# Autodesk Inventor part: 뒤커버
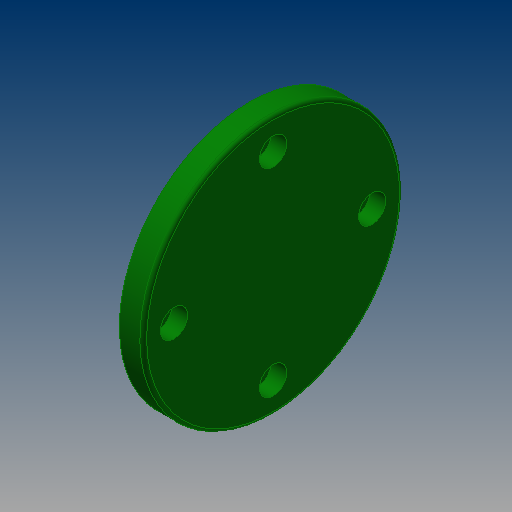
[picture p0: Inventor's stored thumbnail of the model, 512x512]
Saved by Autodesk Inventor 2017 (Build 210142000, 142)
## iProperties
Created: 2015-09
Part Number: 뒤커버
Material: 알루미늄 6061
Document SubType Name: Modeling
Designer: mduedu
Density: 2.71 g/cm^3
Mass: 54.0417 g
Surface Area: 84.9688 cm^2
Volume: 19.9416 cm^3
Appearance: 진녹색
Author: mduedu
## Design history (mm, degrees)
sketch "스케치1"
  geometry: L1 (-15.5, 47)-(-15.5, 85); L2 (-15.5, 85)-(-22.5, 85); L3 (-22.5, 85)-(-22.5, 67); L4 (-25.5, 67)-(-25.5, 47); L5 (-79.5, 39.5)-(-79.5, 54.5) reference; L6 (48.5, 54.5)-(48.5, 39.5) reference; L7 (-79.5, 47)-(48.5, 47); L8 (-22.5, 67)-(-25.5, 67); L9 (-25.5, 47)-(-15.5, 47); 1 further point
  constraints: 14 end point, 4 midpoint, 3 parallel, 1 collinear, 1 point on line, 1 vertical
  dimensions: "d6" = 76 diameter of L2 L7; "d7" = 7 distance of L1.end L2.end; "d8" = 40 diameter of L3.end L7; "d32" = 10 distance between parallel lines of L1 L4
revolve "회전1" sketch "스케치1" stored, may be unused: angle "d4" = 90 deg
sketch "스케치4"
  geometry: C1 r 38 at (0, 0) reference; 2 further points
  constraints: 1 coincident
hole "구멍3" sketch "스케치4" at (0, 0) diameter "d33" = 33; stored, may be unused: countersink angle "d37" = 90 deg, drill point angle "d39" = 0 deg; dims "d34" = 6, "d35" = 4, "d36" = 2, "d38" = 5
fillet "모깎기4" dims "d40" = 1
chamfer "모따기2" distance "d41" = 1; stored, may be unused: second distance "d42" = 2, angle "d43" = 45 deg
sketch "스케치6" dims "d56" = 58
  geometry: C1 r 38 at (0, 0) reference; 5 further points
  constraints: 2 vertical alignment, 1 coincident, 7 other
  dimensions: "d59" = 360 deg dimension on C1.centre point (0, 29) (derived)
sketch "스케치7"
  geometry: 4 further points
  constraints: 4 other
hole "구멍5" sketch "스케치7" at (0, 29), (-29, 0), (29, 0), (0, -29) diameter "d62" = 4.5; stored, may be unused: countersink angle "d66" = 90 deg, drill point angle "d68" = 0 deg; dims "d63" = 6, "d64" = 8, "d65" = 4.6, "d67" = 8
node "솔리드1"
node "참조1"
node "참조2"
